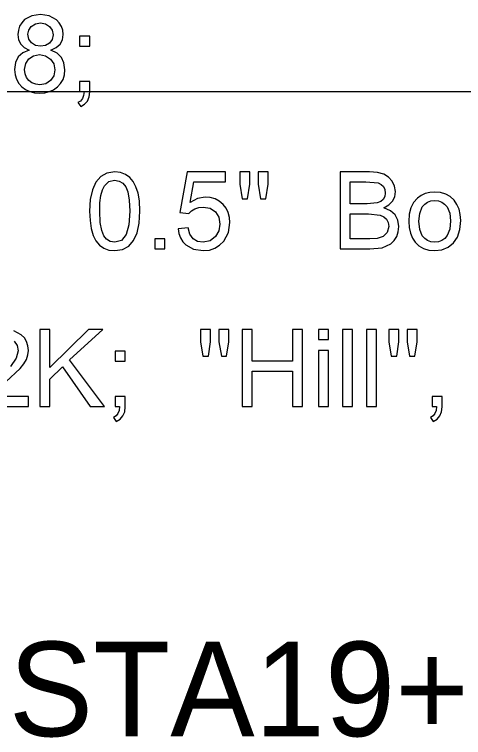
# Model space of a CAD drawing. Extents: x 1001568 to 1002149, y 1840825 to 1841423.
# Drawn here: x 1001907.331 to 1001909.231, y 1840964.734 to 1840967.795 of the extents above; entities that cross this region are included whole.
import ezdxf

# ---------------------------------------------------------------- set-up
doc = ezdxf.new("R2010")
doc.units = 0
for name, color, linetype in [('40', 7, 'Continuous'), ('R_No Plot', 7, 'Continuous'), ('SIGNS', 7, 'Continuous')]:
    doc.layers.add(name, color=color, linetype=linetype)

msp = doc.modelspace()

# ---------------------------------------------------------------- linework, layer by layer
at = {"layer": 'R_No Plot'}
msp.add_line((1001890.6501, 1840967.4691), (1001982.1327, 1840967.4691), dxfattribs=at)
at = {"layer": 'SIGNS'}
for points in [[(1001907.3934, 1840967.6446), (1001907.366, 1840967.6331), (1001907.3465, 1840967.6155), (1001907.3348, 1840967.5917), (1001907.3311, 1840967.562), (1001907.333, 1840967.5402), (1001907.3389, 1840967.5208), (1001907.3486, 1840967.5035), (1001907.3621, 1840967.4887), (1001907.3778, 1840967.477), (1001907.3957, 1840967.4687), (1001907.4155, 1840967.4637), (1001907.4375, 1840967.462), (1001907.4588, 1840967.4636), (1001907.4786, 1840967.4686), (1001907.4963, 1840967.4768), (1001907.5124, 1840967.4885), (1001907.5261, 1840967.5032), (1001907.5361, 1840967.5203), (1001907.5418, 1840967.5395), (1001907.5438, 1840967.5608), (1001907.54, 1840967.59), (1001907.529, 1840967.6137), (1001907.5107, 1840967.6319), (1001907.4851, 1840967.6446), (1001907.5076, 1840967.6555), (1001907.5238, 1840967.6701), (1001907.5334, 1840967.6883), (1001907.5367, 1840967.71), (1001907.5349, 1840967.7284), (1001907.5294, 1840967.745), (1001907.5203, 1840967.7598), (1001907.5078, 1840967.7728), (1001907.4773, 1840967.7897), (1001907.4404, 1840967.7953), (1001907.4036, 1840967.7898), (1001907.3737, 1840967.7733), (1001907.3612, 1840967.7605), (1001907.3523, 1840967.746), (1001907.347, 1840967.7295), (1001907.3453, 1840967.7111), (1001907.3483, 1840967.6886), (1001907.3572, 1840967.6701), (1001907.3722, 1840967.6554), (1001907.3934, 1840967.6446)], [(1001907.3878, 1840967.7115), (1001907.3914, 1840967.7294), (1001907.4019, 1840967.7446), (1001907.4196, 1840967.7561), (1001907.441, 1840967.7599), (1001907.4618, 1840967.756), (1001907.479, 1840967.7449), (1001907.4904, 1840967.7286), (1001907.4942, 1840967.7093), (1001907.4902, 1840967.6896), (1001907.4789, 1840967.6741), (1001907.462, 1840967.6639), (1001907.4414, 1840967.6606), (1001907.4196, 1840967.6641), (1001907.4024, 1840967.675), (1001907.3914, 1840967.6913), (1001907.3878, 1840967.7115)], [(1001907.3736, 1840967.562), (1001907.3782, 1840967.587), (1001907.3915, 1840967.6074), (1001907.4114, 1840967.6208), (1001907.4364, 1840967.6251), (1001907.462, 1840967.6204), (1001907.4829, 1840967.6067), (1001907.4966, 1840967.5861), (1001907.5013, 1840967.5606), (1001907.4967, 1840967.5354), (1001907.4833, 1840967.5152), (1001907.4629, 1840967.5019), (1001907.4378, 1840967.4975), (1001907.4205, 1840967.4995), (1001907.4047, 1840967.5059), (1001907.3909, 1840967.5157), (1001907.3813, 1840967.5284), (1001907.3754, 1840967.5438), (1001907.3736, 1840967.562)], [(1001907.6486, 1840966.9619), (1001907.6503, 1840966.9226), (1001907.6553, 1840966.8887), (1001907.6636, 1840966.8601), (1001907.6754, 1840966.8367), (1001907.6902, 1840966.8184), (1001907.7085, 1840966.8055), (1001907.7301, 1840966.7978), (1001907.755, 1840966.7954), (1001907.7877, 1840966.8002), (1001907.8142, 1840966.8145), (1001907.8348, 1840966.8381), (1001907.8496, 1840966.8706), (1001907.8584, 1840966.9118), (1001907.8614, 1840966.9619), (1001907.8595, 1840967.0055), (1001907.8541, 1840967.0389), (1001907.8448, 1840967.066), (1001907.8329, 1840967.0882), (1001907.8183, 1840967.1055), (1001907.8011, 1840967.118), (1001907.7793, 1840967.1261), (1001907.755, 1840967.1287), (1001907.7221, 1840967.1237), (1001907.6959, 1840967.1095), (1001907.6751, 1840967.0857), (1001907.6604, 1840967.0532), (1001907.6515, 1840967.0119), (1001907.6486, 1840966.9619)], [(1001908.7087, 1840966.8024), (1001908.834, 1840966.8024), (1001908.8863, 1840966.8077), (1001908.923, 1840966.824), (1001908.9377, 1840966.838), (1001908.9483, 1840966.8549), (1001908.9547, 1840966.8745), (1001908.9569, 1840966.897), (1001908.9529, 1840966.9246), (1001908.9411, 1840966.9471), (1001908.9215, 1840966.9641), (1001908.8942, 1840966.9759), (1001908.9154, 1840966.9889), (1001908.9307, 1840967.0049), (1001908.9398, 1840967.0236), (1001908.9427, 1840967.0452), (1001908.9391, 1840967.0679), (1001908.929, 1840967.089), (1001908.9133, 1840967.1065), (1001908.8937, 1840967.1187), (1001908.8667, 1840967.1261), (1001908.8329, 1840967.1287), (1001908.7087, 1840967.1287), (1001908.7087, 1840966.8024)], [(1001907.6912, 1840966.962), (1001907.6924, 1840966.9984), (1001907.6962, 1840967.0287), (1001907.7025, 1840967.0525), (1001907.7115, 1840967.0703), (1001907.7302, 1840967.0876), (1001907.7546, 1840967.0932), (1001907.7733, 1840967.09), (1001907.7889, 1840967.0807), (1001907.8013, 1840967.0653), (1001907.8103, 1840967.0438), (1001907.8166, 1840967.0091), (1001907.8189, 1840966.962), (1001907.8149, 1840966.9044), (1001907.8029, 1840966.8634), (1001907.783, 1840966.8388), (1001907.755, 1840966.8308), (1001907.7362, 1840966.8339), (1001907.7208, 1840966.8432), (1001907.7085, 1840966.8586), (1001907.6997, 1840966.8802), (1001907.6933, 1840966.9147), (1001907.6912, 1840966.962)], [(1001908.7512, 1840966.9939), (1001908.7512, 1840967.0861), (1001908.8182, 1840967.0861), (1001908.8692, 1840967.0818), (1001908.8829, 1840967.0756), (1001908.8926, 1840967.0665), (1001908.8984, 1840967.0543), (1001908.9001, 1840967.0392), (1001908.8978, 1840967.0243), (1001908.8914, 1840967.0124), (1001908.8807, 1840967.0035), (1001908.866, 1840966.9975), (1001908.8237, 1840966.9939), (1001908.7512, 1840966.9939)], [(1001908.9993, 1840966.9194), (1001909.001, 1840966.8931), (1001909.0061, 1840966.8696), (1001909.0145, 1840966.8487), (1001909.0264, 1840966.8309), (1001909.0424, 1840966.8152), (1001909.0617, 1840966.8041), (1001909.0839, 1840966.7975), (1001909.1093, 1840966.7954), (1001909.1387, 1840966.799), (1001909.1659, 1840966.8098), (1001909.1891, 1840966.828), (1001909.2058, 1840966.8529), (1001909.2157, 1840966.8844), (1001909.2192, 1840966.9228), (1001909.2174, 1840966.9479), (1001909.2121, 1840966.9707), (1001909.2032, 1840966.991), (1001909.1909, 1840967.0089), (1001909.1745, 1840967.024), (1001909.1556, 1840967.0348), (1001909.1337, 1840967.0413), (1001909.1093, 1840967.0436), (1001909.0882, 1840967.0419), (1001909.0689, 1840967.0369), (1001909.0513, 1840967.0286), (1001909.0356, 1840967.0172), (1001909.0196, 1840966.999), (1001909.0083, 1840966.9767), (1001909.0015, 1840966.9501), (1001908.9993, 1840966.9194)], [(1001909.0419, 1840966.9195), (1001909.0455, 1840966.9532), (1001909.0567, 1840966.9802), (1001909.0666, 1840966.9923), (1001909.0787, 1840967.0011), (1001909.0929, 1840967.0063), (1001909.1093, 1840967.0081), (1001909.1252, 1840967.0063), (1001909.1392, 1840967.0012), (1001909.1512, 1840966.9926), (1001909.1613, 1840966.9806), (1001909.1727, 1840966.9538), (1001909.1766, 1840966.9209), (1001909.173, 1840966.8866), (1001909.162, 1840966.8594), (1001909.152, 1840966.8468), (1001909.1399, 1840966.8378), (1001909.1257, 1840966.8325), (1001909.1093, 1840966.8308), (1001909.0929, 1840966.8326), (1001909.0787, 1840966.8379), (1001909.0666, 1840966.8465), (1001909.0567, 1840966.8587), (1001909.0455, 1840966.8855), (1001909.0419, 1840966.9195)], [(1001908.7512, 1840966.845), (1001908.7512, 1840966.9514), (1001908.8289, 1840966.9514), (1001908.8778, 1840966.946), (1001908.8939, 1840966.9387), (1001908.9054, 1840966.9284), (1001908.9121, 1840966.9148), (1001908.9143, 1840966.8982), (1001908.9077, 1840966.872), (1001908.891, 1840966.8554), (1001908.8651, 1840966.8464), (1001908.8349, 1840966.845), (1001908.7512, 1840966.845)], [(1001907.2946, 1840966.2399), (1001907.3553, 1840966.2962), (1001907.3701, 1840966.3154), (1001907.3809, 1840966.3347), (1001907.3872, 1840966.3538), (1001907.3894, 1840966.3731), (1001907.3875, 1840966.3927), (1001907.3819, 1840966.4102), (1001907.3725, 1840966.4257), (1001907.3595, 1840966.439), (1001907.3278, 1840966.4563)], [(1001907.329, 1840966.4114), (1001907.3423, 1840966.3933), (1001907.3469, 1840966.3707), (1001907.3385, 1840966.3397), (1001907.314, 1840966.3054)], [(1001907.1766, 1840966.1358), (1001907.3894, 1840966.1358), (1001907.3894, 1840966.1783), (1001907.2324, 1840966.1783)]]:
    msp.add_lwpolyline(points, dxfattribs=at)
for points in [[(1001907.6065, 1840967.6606), (1001907.6491, 1840967.6606), (1001907.6491, 1840967.7031), (1001907.6065, 1840967.7031)], [(1001907.6065, 1840967.4691), (1001907.6249, 1840967.4691), (1001907.6228, 1840967.4524), (1001907.618, 1840967.439), (1001907.6101, 1840967.4289), (1001907.5994, 1840967.4223), (1001907.6108, 1840967.4053), (1001907.6275, 1840967.4152), (1001907.6394, 1840967.4288), (1001907.6466, 1840967.4462), (1001907.6491, 1840967.4676), (1001907.6491, 1840967.5116), (1001907.6065, 1840967.5116)], [(1001908.0227, 1840966.8881), (1001908.0264, 1840966.8673), (1001908.0333, 1840966.8491), (1001908.0433, 1840966.8331), (1001908.0564, 1840966.8196), (1001908.0889, 1840966.8013), (1001908.1292, 1840966.7954), (1001908.1553, 1840966.7979), (1001908.1785, 1840966.8055), (1001908.1989, 1840966.8181), (1001908.2163, 1840966.8359), (1001908.236, 1840966.872), (1001908.2426, 1840966.9141), (1001908.2407, 1840966.9361), (1001908.2353, 1840966.9563), (1001908.2262, 1840966.9745), (1001908.2136, 1840966.9909), (1001908.1975, 1840967.0047), (1001908.1796, 1840967.0145), (1001908.1595, 1840967.0203), (1001908.1376, 1840967.0223), (1001908.1049, 1840967.0164), (1001908.0737, 1840966.9992), (1001908.0897, 1840967.0861), (1001908.2243, 1840967.0861), (1001908.2243, 1840967.1287), (1001908.0616, 1840967.1287), (1001908.0299, 1840966.9571), (1001908.0683, 1840966.9521), (1001908.08, 1840966.9642), (1001908.0942, 1840966.9729), (1001908.1104, 1840966.9779), (1001908.129, 1840966.9797), (1001908.1587, 1840966.9746), (1001908.1812, 1840966.9598), (1001908.1953, 1840966.937), (1001908.2001, 1840966.908), (1001908.1955, 1840966.8787), (1001908.1819, 1840966.8545), (1001908.1591, 1840966.8367), (1001908.1297, 1840966.8308), (1001908.1052, 1840966.8345), (1001908.0863, 1840966.846), (1001908.0732, 1840966.865), (1001908.0656, 1840966.8918)], [(1001908.2944, 1840967.0152), (1001908.3173, 1840967.0152), (1001908.3266, 1840967.0761), (1001908.3266, 1840967.1287), (1001908.284, 1840967.1287), (1001908.284, 1840967.0761)], [(1001908.3722, 1840967.0152), (1001908.3946, 1840967.0152), (1001908.4046, 1840967.0761), (1001908.4046, 1840967.1287), (1001908.3621, 1840967.1287), (1001908.3621, 1840967.0761)], [(1001907.9241, 1840966.8024), (1001907.9667, 1840966.8024), (1001907.9667, 1840966.845), (1001907.9241, 1840966.845)], [(1001907.4379, 1840966.1358), (1001907.4805, 1840966.1358), (1001907.4805, 1840966.2508), (1001907.5334, 1840966.3032), (1001907.6512, 1840966.1358), (1001907.712, 1840966.1358), (1001907.5642, 1840966.3334), (1001907.7043, 1840966.462), (1001907.6436, 1840966.462), (1001907.4805, 1840966.3007), (1001907.4805, 1840966.462), (1001907.4379, 1840966.462)], [(1001908.1284, 1840966.3485), (1001908.1512, 1840966.3485), (1001908.1605, 1840966.4095), (1001908.1605, 1840966.462), (1001908.118, 1840966.462), (1001908.118, 1840966.4095)], [(1001908.2062, 1840966.3485), (1001908.2286, 1840966.3485), (1001908.2385, 1840966.4095), (1001908.2385, 1840966.462), (1001908.196, 1840966.462), (1001908.196, 1840966.4095)], [(1001908.2944, 1840966.1358), (1001908.337, 1840966.1358), (1001908.337, 1840966.2847), (1001908.5072, 1840966.2847), (1001908.5072, 1840966.1358), (1001908.5497, 1840966.1358), (1001908.5497, 1840966.462), (1001908.5072, 1840966.462), (1001908.5072, 1840966.3273), (1001908.337, 1840966.3273), (1001908.337, 1840966.462), (1001908.2944, 1840966.462)], [(1001908.6174, 1840966.4194), (1001908.6599, 1840966.4194), (1001908.6599, 1840966.462), (1001908.6174, 1840966.462)], [(1001908.7189, 1840966.1358), (1001908.7614, 1840966.1358), (1001908.7614, 1840966.462), (1001908.7189, 1840966.462)], [(1001908.8204, 1840966.1358), (1001908.863, 1840966.1358), (1001908.863, 1840966.462), (1001908.8204, 1840966.462)], [(1001908.9253, 1840966.3485), (1001908.9481, 1840966.3485), (1001908.9574, 1840966.4095), (1001908.9574, 1840966.462), (1001908.9148, 1840966.462), (1001908.9148, 1840966.4095)], [(1001909.0031, 1840966.3485), (1001909.0254, 1840966.3485), (1001909.0354, 1840966.4095), (1001909.0354, 1840966.462), (1001908.9929, 1840966.462), (1001908.9929, 1840966.4095)], [(1001907.757, 1840966.3273), (1001907.7995, 1840966.3273), (1001907.7995, 1840966.3698), (1001907.757, 1840966.3698)], [(1001908.6174, 1840966.1358), (1001908.6599, 1840966.1358), (1001908.6599, 1840966.3728), (1001908.6174, 1840966.3728)], [(1001907.757, 1840966.1358), (1001907.7753, 1840966.1358), (1001907.7733, 1840966.1191), (1001907.7684, 1840966.1057), (1001907.7605, 1840966.0956), (1001907.7499, 1840966.0889), (1001907.7613, 1840966.072), (1001907.7779, 1840966.0818), (1001907.7899, 1840966.0955), (1001907.7971, 1840966.1129), (1001907.7995, 1840966.1342), (1001907.7995, 1840966.1783), (1001907.757, 1840966.1783)], [(1001909.0983, 1840966.1358), (1001909.1167, 1840966.1358), (1001909.1147, 1840966.1191), (1001909.1098, 1840966.1057), (1001909.1019, 1840966.0956), (1001909.0913, 1840966.0889), (1001909.1027, 1840966.072), (1001909.1193, 1840966.0818), (1001909.1313, 1840966.0955), (1001909.1385, 1840966.1129), (1001909.1409, 1840966.1342), (1001909.1409, 1840966.1783), (1001909.0983, 1840966.1783)]]:
    msp.add_lwpolyline(points, close=True, dxfattribs=at)

# ---------------------------------------------------------------- texts
at = {"layer": '40'}
msp.add_text('SS-RH-10-STA19+65NB', height=0.4, rotation=0, dxfattribs=at).set_placement((1001904.6912, 1840964.7394))

doc.saveas('drawing.dxf')
